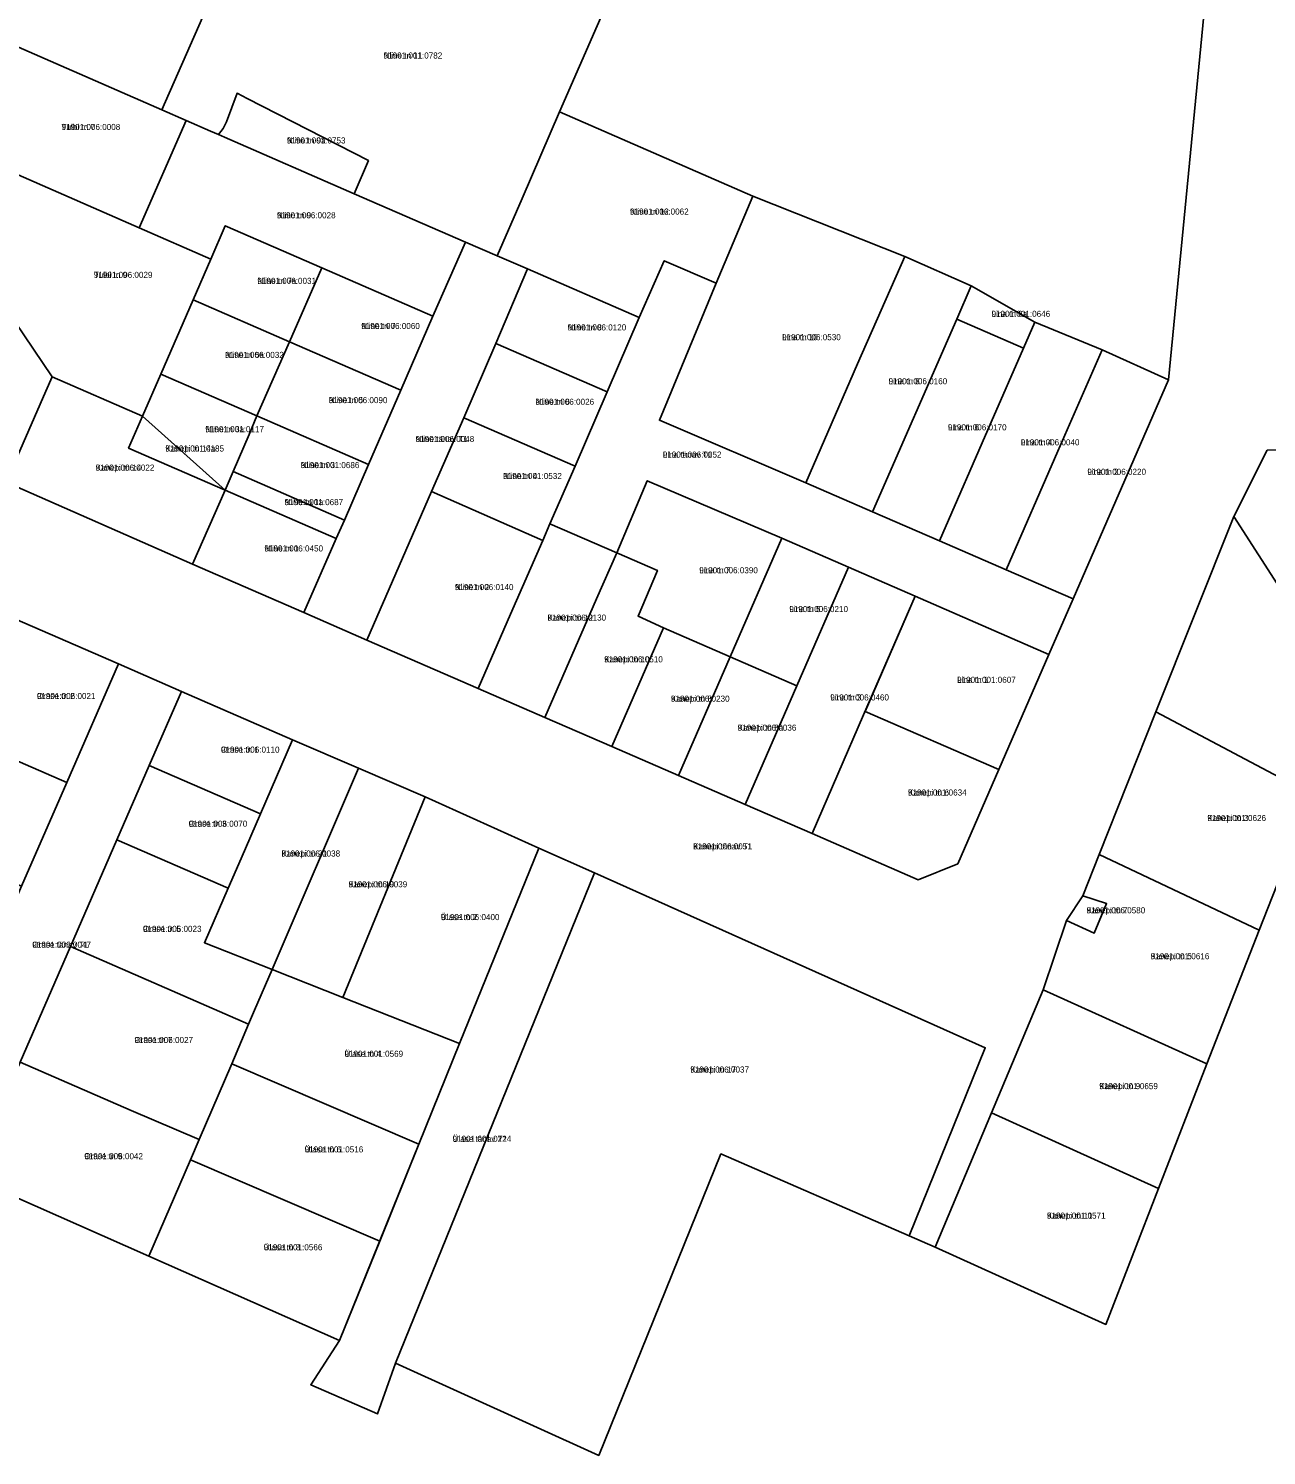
# Model space of a CAD drawing. Extents: x 675810 to 681273, y 6411190 to 6417565.
# Drawn here: x 676085.9 to 676392, y 6416426.2 to 6416779.2 of the extents above; entities that cross this region are included whole.
import ezdxf

# ---------------------------------------------------------------- set-up
doc = ezdxf.new("R2010")
doc.units = 0
for name, color, linetype in [('L_AADRESS', 7, 'Continuous'), ('PIIR', 7, 'Continuous'), ('TUNNUS', 7, 'Continuous')]:
    doc.layers.add(name, color=color, linetype=linetype)

msp = doc.modelspace()

# ---------------------------------------------------------------- linework, layer by layer
at = {"layer": 'PIIR'}
for points in [[(676128.92, 6416781.96), (676145.72, 6416820.6), (676193.25, 6416799.7), (676196.28, 6416806.7), (676231.46, 6416791.28), (676217.23, 6416758.59), (676207.95, 6416737.2), (676201.76, 6416722.97), (676193.96, 6416726.34), (676166.43, 6416738.35), (676169.95, 6416746.52), (676139.99, 6416761.91), (676137.49, 6416763.19), (676134.88, 6416756.11), (676134.07, 6416754.48), (676132.86, 6416752.97), (676130.92, 6416753.82), (676124.9, 6416756.46), (676118.85, 6416759.06)], [(676128.92, 6416781.96), (676118.85, 6416759.06), (676074.89, 6416778.3), (676084.89, 6416801.21)], [(676074.89, 6416778.3), (676118.85, 6416759.06), (676124.9, 6416756.46), (676113.24, 6416729.91), (676063.28, 6416751.72)], [(676134.88, 6416756.11), (676137.49, 6416763.19), (676139.99, 6416761.91), (676169.95, 6416746.52), (676166.43, 6416738.35), (676134.34, 6416752.32), (676132.86, 6416752.97), (676134.07, 6416754.48)], [(676217.23, 6416758.59), (676264.99, 6416737.74), (676255.96, 6416716.25), (676243.12, 6416721.78), (676236.92, 6416707.76), (676209.26, 6416719.73), (676201.76, 6416722.97), (676207.95, 6416737.2)], [(676124.9, 6416756.46), (676130.92, 6416753.82), (676132.86, 6416752.97), (676134.34, 6416752.32), (676166.43, 6416738.35), (676193.96, 6416726.34), (676185.91, 6416708.05), (676158.41, 6416720.02), (676134.57, 6416730.4), (676130.99, 6416722.19), (676113.24, 6416729.91)], [(676063.28, 6416751.72), (676113.24, 6416729.91), (676130.99, 6416722.19), (676126.59, 6416712.06), (676118.62, 6416693.7), (676114.1, 6416683.32), (676091.78, 6416693.01), (676075.42, 6416717.09), (676058.88, 6416741.63)], [(676264.99, 6416737.74), (676302.6, 6416722.78), (676290.89, 6416696.22), (676278.1, 6416666.84), (676241.9, 6416682.32), (676255.96, 6416716.25)], [(676134.57, 6416730.4), (676158.41, 6416720.02), (676150.43, 6416701.69), (676126.59, 6416712.06), (676130.99, 6416722.19)], [(676035.06, 6416686.57), (676052.52, 6416727.12), (676075.42, 6416717.09), (676091.78, 6416693.01), (676090.23, 6416689.47), (676080.36, 6416666.96)], [(676185.91, 6416708.05), (676193.96, 6416726.34), (676201.76, 6416722.97), (676209.26, 6416719.73), (676201.5, 6416701.27), (676193.51, 6416682.94), (676185.54, 6416664.64), (676169.59, 6416627.93), (676153.99, 6416634.7), (676161.98, 6416653.01), (676164.02, 6416657.55), (676169.96, 6416671.37), (676177.93, 6416689.71)], [(676302.6, 6416722.78), (676319.03, 6416715.59), (676315.41, 6416707.3), (676294.57, 6416659.66), (676278.1, 6416666.84), (676290.89, 6416696.22)], [(676150.43, 6416701.69), (676158.41, 6416720.02), (676185.91, 6416708.05), (676177.93, 6416689.71)], [(676209.26, 6416719.73), (676236.92, 6416707.76), (676229.02, 6416689.3), (676201.5, 6416701.27)], [(676243.12, 6416721.78), (676255.96, 6416716.25), (676241.9, 6416682.32), (676278.1, 6416666.84), (676294.57, 6416659.66), (676311.18, 6416652.49), (676327.68, 6416645.31), (676344.19, 6416638.13), (676338.22, 6416624.34), (676305.18, 6416638.74), (676288.68, 6416645.92), (676272.16, 6416653.11), (676238.89, 6416667.32), (676231.35, 6416649.53), (676214.84, 6416656.71), (676221.04, 6416670.96), (676229.02, 6416689.3), (676236.92, 6416707.76)], [(676334.7, 6416706.55), (676331.93, 6416700.17), (676315.41, 6416707.3), (676319.03, 6416715.59)], [(676126.59, 6416712.06), (676150.43, 6416701.69), (676142.4, 6416683.38), (676118.62, 6416693.7)], [(676294.57, 6416659.66), (676315.41, 6416707.3), (676331.93, 6416700.17), (676323.95, 6416681.83), (676311.18, 6416652.49)], [(676311.18, 6416652.49), (676323.95, 6416681.83), (676331.93, 6416700.17), (676334.7, 6416706.55), (676351.35, 6416699.69), (676340.46, 6416674.65), (676327.68, 6416645.31)], [(676169.96, 6416671.37), (676142.4, 6416683.38), (676150.43, 6416701.69), (676177.93, 6416689.71)], [(676201.5, 6416701.27), (676229.02, 6416689.3), (676221.04, 6416670.96), (676193.51, 6416682.94)], [(676327.68, 6416645.31), (676340.46, 6416674.65), (676351.35, 6416699.69), (676367.77, 6416692.32), (676356.96, 6416667.47), (676344.19, 6416638.13)], [(676091.78, 6416693.01), (676114.1, 6416683.32), (676110.64, 6416675.41), (676134.51, 6416664.99), (676126.49, 6416646.66), (676080.36, 6416666.96), (676090.23, 6416689.47)], [(676136.49, 6416669.59), (676134.51, 6416664.99), (676114.1, 6416683.32), (676118.62, 6416693.7), (676142.4, 6416683.38), (676140.5, 6416678.79)], [(676110.64, 6416675.41), (676114.1, 6416683.32), (676134.51, 6416664.99)], [(676140.5, 6416678.79), (676142.4, 6416683.38), (676169.96, 6416671.37), (676164.02, 6416657.55), (676136.49, 6416669.59)], [(676214.84, 6416656.71), (676213.06, 6416652.57), (676185.54, 6416664.64), (676193.51, 6416682.94), (676221.04, 6416670.96)], [(676420.49, 6416675.53), (676454.05, 6416625.13), (676419.82, 6416602.76), (676383.9, 6416658.49), (676392.2, 6416674.9)], [(676134.51, 6416664.99), (676136.49, 6416669.59), (676164.02, 6416657.55), (676161.98, 6416653.01)], [(676241.4, 6416645.17), (676231.35, 6416649.53), (676238.89, 6416667.32), (676272.16, 6416653.11), (676259.4, 6416623.76), (676242.89, 6416630.94), (676236.65, 6416633.86)], [(676126.49, 6416646.66), (676134.51, 6416664.99), (676161.98, 6416653.01), (676153.99, 6416634.7)], [(676213.06, 6416652.57), (676205.08, 6416634.29), (676197.1, 6416615.95), (676169.59, 6416627.93), (676185.54, 6416664.64)], [(676197.1, 6416615.95), (676205.08, 6416634.29), (676213.06, 6416652.57), (676214.84, 6416656.71), (676231.35, 6416649.53), (676226.38, 6416638.12), (676213.61, 6416608.77)], [(676383.9, 6416658.49), (676419.82, 6416602.76), (676403.38, 6416589.64), (676364.69, 6416610.15)], [(676288.68, 6416645.92), (676275.91, 6416616.58), (676259.4, 6416623.76), (676272.16, 6416653.11)], [(676226.38, 6416638.12), (676231.35, 6416649.53), (676241.4, 6416645.17), (676236.65, 6416633.86), (676242.89, 6416630.94), (676230.12, 6416601.59), (676213.61, 6416608.77)], [(676292.41, 6416609.4), (676279.64, 6416580.06), (676263.13, 6416587.24), (676275.91, 6416616.58), (676288.68, 6416645.92), (676305.18, 6416638.74)], [(676305.18, 6416638.74), (676338.22, 6416624.34), (676325.86, 6416595.94), (676292.8, 6416610.29)], [(676080.6, 6416633.98), (676108.12, 6416622.01), (676095.35, 6416592.67), (676067.83, 6416604.64), (676072.63, 6416615.65)], [(676230.12, 6416601.59), (676242.89, 6416630.94), (676259.4, 6416623.76), (676246.63, 6416594.42)], [(676259.4, 6416623.76), (676275.91, 6416616.58), (676263.13, 6416587.24), (676246.63, 6416594.42)], [(676108.12, 6416622.01), (676123.72, 6416615.22), (676115.74, 6416596.89), (676107.76, 6416578.54), (676096.26, 6416552.11), (676083.82, 6416523.52), (676071.48, 6416495.08), (676075.95, 6416493.1), (676070.21, 6416479.42), (676049.98, 6416488.07), (676055.94, 6416501.84), (676068.31, 6416530.27), (676076.19, 6416548.67), (676084.17, 6416567), (676095.35, 6416592.67)], [(676123.72, 6416615.22), (676151.22, 6416603.25), (676143.24, 6416584.91), (676115.74, 6416596.89)], [(676051.45, 6416611.74), (676067.83, 6416604.64), (676095.35, 6416592.67), (676084.17, 6416567), (676056.67, 6416578.98), (676042.92, 6416584.97), (676040.69, 6416585.8)], [(676279.64, 6416580.06), (676292.41, 6416609.4), (676292.8, 6416610.29), (676325.86, 6416595.94), (676315.67, 6416572.54), (676305.9, 6416568.63)], [(676403.38, 6416589.64), (676390.24, 6416556.16), (676350.65, 6416574.84), (676364.69, 6416610.15)], [(676151.22, 6416603.25), (676167.53, 6416596.21), (676146.14, 6416546.43), (676129.39, 6416553.06), (676135.26, 6416566.57), (676138.45, 6416573.91), (676143.24, 6416584.91)], [(676138.45, 6416573.91), (676135.26, 6416566.57), (676107.76, 6416578.54), (676115.74, 6416596.89), (676143.24, 6416584.91)], [(676167.53, 6416596.21), (676183.97, 6416589.1), (676163.6, 6416539.53), (676146.14, 6416546.43)], [(676212.12, 6416576.48), (676192.51, 6416528.09), (676163.6, 6416539.53), (676183.97, 6416589.1)], [(676107.76, 6416578.54), (676135.26, 6416566.57), (676129.39, 6416553.06), (676146.14, 6416546.43), (676141.79, 6416536.33), (676140.33, 6416532.92), (676116.89, 6416543.12), (676096.26, 6416552.11)], [(676225.82, 6416570.35), (676176.65, 6416449), (676172.19, 6416436.48), (676155.7, 6416443.7), (676162.78, 6416454.6), (676182.46, 6416503.24), (676192.51, 6416528.09), (676212.12, 6416576.48)], [(676342.59, 6416558.56), (676349.37, 6416555.41), (676352.46, 6416562.71), (676346.58, 6416564.68), (676350.65, 6416574.84), (676390.24, 6416556.16), (676377.26, 6416523.07), (676336.82, 6416541.39)], [(676225.82, 6416570.35), (676322.47, 6416527.05), (676303.63, 6416480.57), (676257.11, 6416500.79), (676226.9, 6416426.2), (676176.65, 6416449)], [(676352.46, 6416562.71), (676349.37, 6416555.41), (676342.59, 6416558.56), (676346.58, 6416564.68)], [(676096.26, 6416552.11), (676116.89, 6416543.12), (676140.33, 6416532.92), (676136.14, 6416523.12), (676128.08, 6416504.36), (676111.32, 6416511.55), (676083.82, 6416523.52)], [(676192.51, 6416528.09), (676182.46, 6416503.24), (676136.14, 6416523.12), (676140.33, 6416532.92), (676141.79, 6416536.33), (676146.14, 6416546.43), (676163.6, 6416539.53)], [(676336.82, 6416541.39), (676377.26, 6416523.07), (676365.32, 6416492.25), (676324.02, 6416510.96)], [(676083.82, 6416523.52), (676111.32, 6416511.55), (676128.08, 6416504.36), (676125.94, 6416499.31), (676115.68, 6416475.47), (676075.95, 6416493.1), (676071.48, 6416495.08)], [(676182.46, 6416503.24), (676172.74, 6416479.22), (676125.94, 6416499.31), (676128.08, 6416504.36), (676136.14, 6416523.12)], [(676365.32, 6416492.25), (676352.31, 6416458.62), (676310.06, 6416477.76), (676324.02, 6416510.96)], [(676172.74, 6416479.22), (676162.78, 6416454.6), (676115.68, 6416475.47), (676125.94, 6416499.31)]]:
    msp.add_lwpolyline(points, close=True, dxfattribs=at)
for points in [[(676080.36, 6416666.96), (676126.49, 6416646.66), (676153.99, 6416634.7), (676169.59, 6416627.93), (676197.1, 6416615.95), (676213.61, 6416608.77), (676230.12, 6416601.59), (676246.63, 6416594.42), (676263.13, 6416587.24), (676279.64, 6416580.06), (676305.9, 6416568.63), (676315.67, 6416572.54), (676325.86, 6416595.94), (676338.22, 6416624.34), (676344.19, 6416638.13), (676356.96, 6416667.47), (676367.77, 6416692.32), (676379.43, 6416812.35)], [(676379.43, 6416812.35), (676367.77, 6416692.32), (676351.35, 6416699.69), (676334.7, 6416706.55), (676319.03, 6416715.59), (676302.6, 6416722.78), (676264.99, 6416737.74), (676217.23, 6416758.59), (676231.46, 6416791.28)], [(676392.2, 6416674.9), (676383.9, 6416658.49), (676364.69, 6416610.15), (676350.65, 6416574.84), (676346.58, 6416564.68), (676342.59, 6416558.56), (676336.82, 6416541.39), (676324.02, 6416510.96), (676310.06, 6416477.76), (676303.63, 6416480.57), (676322.47, 6416527.05), (676225.82, 6416570.35), (676212.12, 6416576.48), (676183.97, 6416589.1), (676167.53, 6416596.21), (676151.22, 6416603.25), (676123.72, 6416615.22), (676108.12, 6416622.01), (676080.6, 6416633.98)], [(676075.95, 6416493.1), (676115.68, 6416475.47), (676162.78, 6416454.6), (676155.7, 6416443.7), (676172.19, 6416436.48), (676176.65, 6416449), (676226.9, 6416426.2), (676257.11, 6416500.79), (676303.63, 6416480.57), (676310.06, 6416477.76), (676352.31, 6416458.62), (676365.32, 6416492.25), (676377.26, 6416523.07), (676390.24, 6416556.16), (676403.38, 6416589.64)]]:
    msp.add_lwpolyline(points, dxfattribs=at)

# ---------------------------------------------------------------- texts
at = {"layer": 'L_AADRESS'}
for s, p in [('Niine tn 11', (676173.71, 6416771.79)), ('Tulbi tn 7', (676094.09, 6416754.11)), ('Niine tn 9a', (676149.79, 6416750.77)), ('Niine tn 9', (676147.34, 6416732.26)), ('Niine tn 12', (676234.64, 6416733.18)), ('Tulbi tn 9', (676102.05, 6416717.52)), ('Niine tn 7a', (676142.5, 6416716.04)), ('Lina tn 6a', (676324.03, 6416707.88)), ('Niine tn 7', (676168.17, 6416704.87)), ('Niine tn 8', (676219.2, 6416704.52)), ('Lina tn 10', (676272.25, 6416702.1)), ('Niine tn 5a', (676134.53, 6416697.72)), ('Lina tn 8', (676298.57, 6416691.21)), ('Niine tn 5', (676160.16, 6416686.53)), ('Niine tn 6', (676211.26, 6416686.12)), ('Niine tn 3a', (676129.63, 6416679.34)), ('Lina tn 6', (676313.25, 6416679.8)), ('Niine tänav T1', (676181.62, 6416676.92)), ('Lina tn 4', (676331.27, 6416676.09)), ('Kanepi tn 14a', (676119.75, 6416674.57)), ('Lina tänav T1', (676242.75, 6416673.06)), ('Kanepi tn 14', (676102.52, 6416669.84)), ('Niine tn 3', (676153.22, 6416670.46)), ('Niine tn 4', (676203.27, 6416667.76)), ('Lina tn 2', (676347.73, 6416668.8)), ('Niine tn 1a', (676149.21, 6416661.3)), ('Niine tn 1', (676144.24, 6416649.84)), ('Lina tn 7', (676251.75, 6416644.45)), ('Niine tn 2', (676191.33, 6416640.28)), ('Kanepi tn 12', (676214.23, 6416632.73)), ('Lina tn 5', (676274.04, 6416634.84)), ('Kanepi tn 10', (676228.25, 6416622.41)), ('Lina tn 1', (676315.52, 6416617.34)), ('Orase tn 2', (676087.97, 6416613.33)), ('Kanepi tn 8', (676244.76, 6416612.68)), ('Lina tn 3', (676284.16, 6416612.98)), ('Kanepi tn 8a', (676261.27, 6416605.5)), ('Orase tn 1', (676133.48, 6416600.07)), ('Kanepi tn 6', (676303.38, 6416589.46)), ('Kanepi tn 3', (676377.4, 6416583.15)), ('Orase tn 3', (676125.5, 6416581.73)), ('Kanepi tänav T1', (676250.25, 6416576.13)), ('Kanepi tn 21', (676148.46, 6416574.37)), ('Kanepi tn 19', (676165.05, 6416566.76)), ('Ülase tn 2', (676187.86, 6416558.64)), ('Kanepi tn 7', (676347.53, 6416560.32)), ('Orase tn 5', (676114.19, 6416555.73)), ('Orase tänav T1', (676086.85, 6416551.82)), ('Kanepi tn 5', (676363.39, 6416548.96)), ('Orase tn 7', (676112.1, 6416528.24)), ('Ülase tn 4', (676164.03, 6416524.83)), ('Kanepi tn 17', (676249.56, 6416520.93)), ('Kanepi tn 9', (676350.66, 6416516.82)), ('Ülase tänav T1', (676190.76, 6416503.79)), ('Orase tn 9', (676099.71, 6416499.49)), ('Ülase tn 6', (676154.18, 6416501.17)), ('Kanepi tn 11', (676337.73, 6416484.79)), ('Ülase tn 8', (676144.07, 6416476.96))]:
    msp.add_text(s, height=1.5, dxfattribs=at).set_placement(p)
at = {"layer": 'TUNNUS'}
for s, p in [('91901:001:0782', (676173.71, 6416771.79)), ('91901:006:0008', (676094.09, 6416754.11)), ('91901:001:0753', (676149.79, 6416750.77)), ('91901:006:0028', (676147.34, 6416732.26)), ('91901:006:0062', (676234.64, 6416733.18)), ('91901:006:0029', (676102.05, 6416717.52)), ('91901:006:0031', (676142.5, 6416716.04)), ('91901:001:0646', (676324.03, 6416707.88)), ('91901:006:0060', (676168.17, 6416704.87)), ('91901:006:0120', (676219.2, 6416704.52)), ('91901:006:0530', (676272.25, 6416702.1)), ('91901:006:0032', (676134.53, 6416697.72)), ('91901:006:0160', (676298.57, 6416691.21)), ('91901:006:0090', (676160.16, 6416686.53)), ('91901:006:0026', (676211.26, 6416686.12)), ('91901:001:0117', (676129.63, 6416679.34)), ('91901:006:0170', (676313.25, 6416679.8)), ('91901:006:0048', (676181.62, 6416676.92)), ('91901:006:0040', (676331.27, 6416676.09)), ('91901:001:0185', (676119.75, 6416674.57)), ('91901:006:0052', (676242.75, 6416673.06)), ('91901:006:0022', (676102.52, 6416669.84)), ('91901:001:0686', (676153.22, 6416670.46)), ('91901:001:0532', (676203.27, 6416667.76)), ('91901:006:0220', (676347.73, 6416668.8)), ('91901:001:0687', (676149.21, 6416661.3)), ('91901:006:0450', (676144.24, 6416649.84)), ('91901:006:0390', (676251.75, 6416644.45)), ('91901:006:0140', (676191.33, 6416640.28)), ('91901:006:0130', (676214.23, 6416632.73)), ('91901:006:0210', (676274.04, 6416634.84)), ('91901:006:0510', (676228.25, 6416622.41)), ('91901:001:0607', (676315.52, 6416617.34)), ('91901:006:0021', (676087.97, 6416613.33)), ('91901:006:0230', (676244.76, 6416612.68)), ('91901:006:0460', (676284.16, 6416612.98)), ('91901:006:0036', (676261.27, 6416605.5)), ('91901:006:0110', (676133.48, 6416600.07)), ('91901:001:0634', (676303.38, 6416589.46)), ('91901:001:0626', (676377.4, 6416583.15)), ('91901:006:0070', (676125.5, 6416581.73)), ('91901:006:0051', (676250.25, 6416576.13)), ('91901:006:0038', (676148.46, 6416574.37)), ('91901:006:0039', (676165.05, 6416566.76)), ('91901:006:0400', (676187.86, 6416558.64)), ('91901:006:0580', (676347.53, 6416560.32)), ('91901:006:0023', (676114.19, 6416555.73)), ('91901:006:0047', (676086.85, 6416551.82)), ('91901:001:0616', (676363.39, 6416548.96)), ('91901:006:0027', (676112.1, 6416528.24)), ('91901:001:0569', (676164.03, 6416524.83)), ('91901:006:0037', (676249.56, 6416520.93)), ('91901:001:0659', (676350.66, 6416516.82)), ('91901:001:0224', (676190.76, 6416503.79)), ('91901:006:0042', (676099.71, 6416499.49)), ('91901:001:0516', (676154.18, 6416501.17)), ('91901:001:0571', (676337.73, 6416484.79)), ('91901:001:0566', (676144.07, 6416476.96))]:
    msp.add_text(s, height=1.5, dxfattribs=at).set_placement(p)

doc.saveas('drawing.dxf')
